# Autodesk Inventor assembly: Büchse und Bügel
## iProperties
Created: 2007-12
Part Number: Büchse und Bügel
Document SubType Name: Assembly
Designer: Benno
Manufacturer: Standard
Standards Organization: Custom
Author: Benno
